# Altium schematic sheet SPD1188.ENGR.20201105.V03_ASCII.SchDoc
size A3; Revision: V03; SheetNumber: 1; SheetTotal: 1
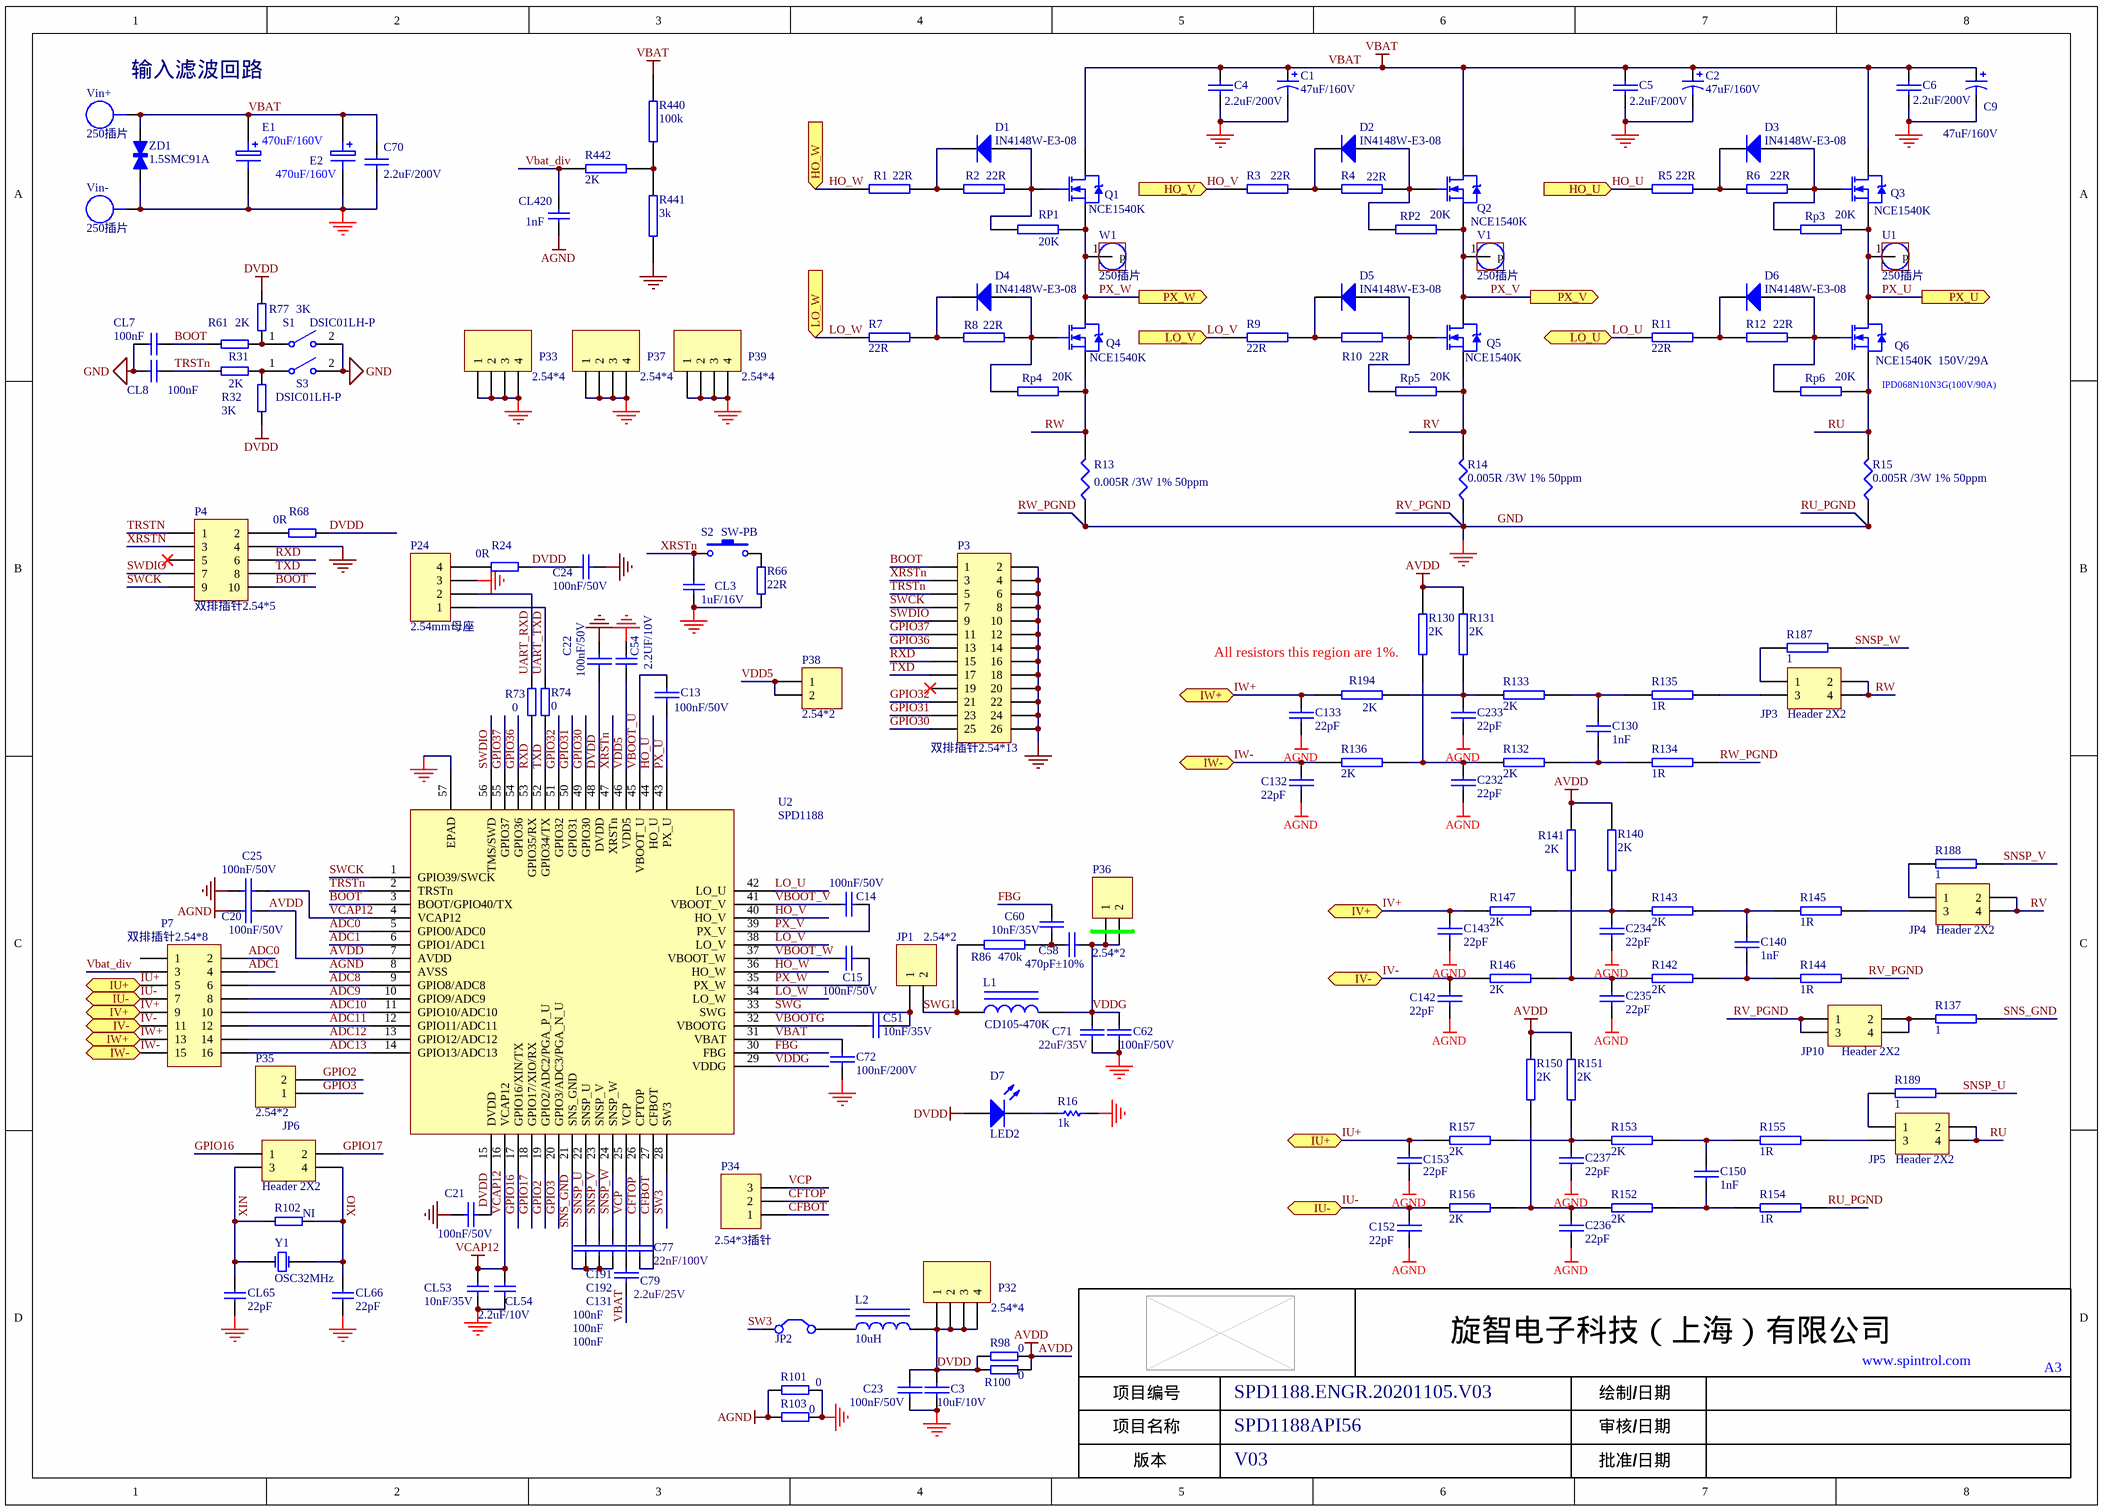
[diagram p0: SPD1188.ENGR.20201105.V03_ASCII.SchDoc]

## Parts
C1  47uF/160V  [RB5.0/10]
C2  47uF/160V  [RB5.0/10]
C3  10uF/10V  [0805]
C4  2.2uF/200V  [2220]
C5  2.2uF/200V  [2220]
C6  2.2uF/200V  [2220]
C9  47uF/160V  [RB5.0/10]
C13  100nF/50V  [0603]
C14  100nF/50V  [0603]
C15  100nF/50V  [0603]
C20  100nF/50V  [0603]
C21  100nF/50V  [0603]
C22  100nF/50V  [0603]
C23  100nF/50V  [0603]
C24  100nF/50V  [0603]
C25  100nF/50V  [0603]
C51  10nF/35V  [0603]
C54  2.2UF/10V  [0603]
C58  470pF±10%  [0603]
C60  10nF/35V  [0603]
C62  100nF/50V  [0603]
C70  2.2uF/200V  [2220]
C71  22uF/35V  [1206]
C72  100nF/200V  [1206]
C77  22nF/100V  [0805]
C79  2.2uF/25V  [0805]
C130  1nF  [0603]
C131  100nF  [0603]
C132  22pF  [0603]
C133  22pF  [0603]
C140  1nF  [0603]
C142  22pF  [0603]
C143  22pF  [0603]
C150  1nF  [0603]
C152  22pF  [0603]
C153  22pF  [0603]
C191  100nF  [0603]
C192  100nF  [0603]
C232  22pF  [0603]
C233  22pF  [0603]
C234  22pF  [0603]
C235  22pF  [0603]
C236  22pF  [0603]
C237  22pF  [0603]
CL3  1uF/16V  [0603]
CL7  100nF  [0603]
CL8  100nF  [0603]
CL53  10nF/35V  [0603]
CL54  2.2uF/10V  [0603]
CL65  CAP CER 20PF 10V  [0603]  (value not drawn)
CL66  CAP CER 20PF 10V  [0603]  (value not drawn)
CL420  1nF  [0603]
D1  IN4148W-E3-08  [LL-34]
D2  IN4148W-E3-08  [LL-34]
D3  IN4148W-E3-08  [LL-34]
D4  IN4148W-E3-08  [LL-34]
D5  IN4148W-E3-08  [LL-34]
D6  IN4148W-E3-08  [LL-34]
D7  LED2  [LED0805]
E1  470uF/160V  [470uF_100V]
E2  470uF/160V  [470uF_100V]
JP1  2.54*2  [CON2]
JP2  Jumper  [CON2]  (value not drawn)
JP3  Header 2X2  [HDR2X2]
JP4  Header 2X2  [HDR2X2]
JP5  Header 2X2  [HDR2X2]
JP6  Header 2X2  [HDR2X2]
JP10  Header 2X2  [HDR2X2]
L1  CD105-470K  [CD105]
L2  10uH  [CD105]
P3  双排插针2.54*13  [HDR2X13]
P4  双排插针2.54*5  [HDR2X5]
P7  双排插针2.54*8  [HDR2X8]
P24  2.54mm母座  [HDR1X4]
P32  2.54*4  [HDR1X4]
P33  2.54*4  [HDR1X4]
P34  2.54*3插针  [2.54*3]
P35  2.54*2  [CON2]
P36  2.54*2  [CON2]
P37  2.54*4  [HDR1X4]
P38  2.54*2  [CON2]
P39  2.54*4  [HDR1X4]
Q1  NCE1540K  [TO-252]
Q2  NCE1540K  [TO-252]
Q3  NCE1540K  [TO-252]
Q4  NCE1540K  [TO-252]
Q5  NCE1540K  [TO-252]
Q6  NCE1540K  150V/29A  [TO-252]
R1  22R  [0603]
R2  22R  [0603]
R3  22R  [0603]
R4  22R  [0603]
R5  22R  [0603]
R6  22R  [0603]
R7  22R  [0603]
R8  22R  [0603]
R9  22R  [0603]
R10  22R  [0603]
R11  22R  [0603]
R12  22R  [0603]
R13  0.005R /3W 1% 50ppm  [2512]
R14  0.005R /3W 1% 50ppm  [2512]
R15  0.005R /3W 1% 50ppm  [2512]
R16  1k  [0603]
R24  0R  [0603]
R31  2K  [0603]
R32  3K  [0603]
R61  2K  [0603]
R66  22R  [0603]
R68  0R  [0603]
R73  RES SMD 0.0OHM  [0603]  (value not drawn)
R74  RES SMD 0.0OHM  [0603]  (value not drawn)
R77  3K  [0603]
R86  470k  [0603]
R98  RES SMD 0.0OHM  [0603]  (value not drawn)
R100  RES SMD 0.0OHM  [0603]  (value not drawn)
R101  RES SMD 0.0OHM  [0603]  (value not drawn)
R102  NI  [0603]
R103  RES SMD 0.0OHM  [0603]  (value not drawn)
R130  2K  [0603]
R131  2K  [0603]
R132  2K  [0603]
R133  2K  [0603]
R134  1R  [0603]
R135  1R  [0603]
R136  2K  [0603]
R137  1  [0603]
R140  2K  [0603]
R141  2K  [0603]
R142  2K  [0603]
R143  2K  [0603]
R144  1R  [0603]
R145  1R  [0603]
R146  2K  [0603]
R147  2K  [0603]
R150  2K  [0603]
R151  2K  [0603]
R152  2K  [0603]
R153  2K  [0603]
R154  1R  [0603]
R155  1R  [0603]
R156  2K  [0603]
R157  2K  [0603]
R187  1  [0603]
R188  1  [0603]
R189  1  [0603]
R194  2K  [0603]
R440  100k  [0805]
R441  3k  [0603]
R442  2K  [0603]
RP1  20K  [0603]
RP2  20K  [0603]
Rp3  20K  [0603]
Rp4  20K  [0603]
Rp5  20K  [0603]
Rp6  20K  [0603]
S1  DSIC01LH-P  [S7.62*1]
S2  SW-PB  [SWITCH-4]
S3  DSIC01LH-P  [S7.62*1]
U1  250插片  [PIN_L]
U2  SPD1188  [QFN56L_20190222]
V1  250插片  [PIN_L]
Vin+  250插片  [PIN_L]
Vin-  250插片  [PIN_L]
W1  250插片  [PIN_L]
Y1  OSC32MHz  [OSC]
ZD1  1.5SMC91A  [SMCTVS]

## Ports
HO_U (in), HO_V (in), HO_W (in), IU+ (bidir), IU- (bidir), IV+ (bidir), IV- (bidir), IW+ (bidir), IW- (bidir), LO_U (bidir), LO_V (in), LO_W (in), PX_U (out), PX_V (out), PX_W (out)

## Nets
AGND: C20.1 C132.2 C133.2 C142.2 C143.2 C152.2 C153.2 C232.2 C233.1 C234.2 C235.1 C236.2 C237.1 CL420.1 R101.2 R103.2 U2.8(AVSS)
AVDD: C20.2 R98.1 R100.1 R130.2 R131.2 R140.1 R141.2 R150.2 R151.2 U2.7(AVDD)
DVDD: C3.2 C21.2 C22.2 C23.2 C24.2 D7.1(A) L2.2 P32.1 P32.2 P32.3 P32.4 R24.2 R32.1 R68.2 R77.1 R98.2 R100.2 U2.15(DVDD) U2.48(DVDD)
GND: C1.2 C2.2 C3.1 C4.2 C5.2 C6.2 C9.2 C21.1 C22.1 C23.1 C24.1 C25.1 C54.1 C62.1 C70.2 C71.2 C72.2 CL3.1 CL7.2 CL8.2 CL53.1 CL54.1 CL65.1 CL66.1 E1.2 E2.2 JP10.1 JP10.3 P3.2 P3.4 P3.6 P3.8 P3.10 P3.12 P3.14 P3.16 P3.18 P3.20 P3.22 P3.24 P3.26 P4.4 P24.3 P33.1 P33.2 P33.3 P33.4 P37.1 P37.2 P37.3 P37.4 P39.1 P39.2 P39.3 P39.4 R13.1 R14.1 R15.1 R16.1 R66.2 R101.1 R103.1 R134.1 R144.1 R154.1 R441.1 S1.2 S3.2 U2.57(EPAD) Vin-.1 ZD1.2  [also labelled RU_PGND, RV_PGND, RW_PGND]
VBAT: C1.1 C2.1 C4.1 C5.1 C6.1 C9.1 C70.1 C72.1 C79.2 E1.1 E2.1 Q1.2(D) Q2.2(D) Q3.2(D) R440.2 U2.31(VBAT) Vin+.1 ZD1.1
VCAP12: C25.2 CL53.2 CL54.2 U2.4(VCAP12) U2.16(VCAP12)
ADC0: P7.2 U2.5(GPIO0/ADC0)
ADC1: P7.4 U2.6(GPIO1/ADC1)
ADC8: P7.6 U2.9(GPIO8/ADC8)
ADC9: P7.8 U2.10(GPIO9/ADC9)
ADC10: P7.10 U2.11(GPIO10/ADC10)
ADC11: P7.12 U2.12(GPIO11/ADC11)
ADC12: P7.14 U2.13(GPIO12/ADC12)
ADC13: P7.16 U2.14(GPIO13/ADC13)
BOOT: CL7.1 P3.1 P4.10 R61.1 U2.3(BOOT/GPIO40/TX)
CFBOT: C77.2 P34.1 U2.27(CFBOT)
CFTOP: C77.1 P34.2 U2.26(CPTOP)
FBG: C60.2 U2.30(FBG)
GPIO2: P35.2 U2.19(GPIO2/ADC2/PGA_P_U)
GPIO3: P35.1 U2.20(GPIO3/ADC3/PGA_N_U)
GPIO16: JP6.1 U2.17(GPIO16/XIN/TX)
GPIO17: JP6.2 U2.18(GPIO17/XIO/RX)
GPIO30: P3.25 U2.49(GPIO30)
GPIO31: P3.23 U2.50(GPIO31)
GPIO32: P3.21 U2.51(GPIO32)
GPIO36: P3.13 U2.54(GPIO36)
GPIO37: P3.11 U2.55(GPIO37)
HO_U: R5.1 U2.44(HO_U) ; port HO_U
HO_V: R3.1 U2.40(HO_V) ; port HO_V
HO_W: R1.1 U2.36(HO_W) ; port HO_W
IU+: C153.1 P7.5 R157.2 ; port IU+
IU-: C152.1 P7.7 R156.2 ; port IU-
IV+: C143.1 P7.9 R147.2 ; port IV+
IV-: C142.1 P7.11 R146.2 ; port IV-
IW+: C133.1 P7.13 R194.2 ; port IW+
IW-: C132.1 P7.15 R136.2 ; port IW-
LO_U: R11.1 U2.42(LO_U) ; port LO_U
LO_V: R9.1 U2.38(LO_V) ; port LO_V
LO_W: R7.1 U2.34(LO_W) ; port LO_W
PX_U: C13.2 Q3.3(S) Q6.2(D) Rp3.2 U1.1(p) U2.43(PX_U) ; port PX_U
PX_V: C14.2 Q2.3(S) Q5.2(D) RP2.2 U2.39(PX_V) V1.1(p) ; port PX_V
PX_W: C15.2 Q1.3(S) Q4.2(D) RP1.2 U2.35(PX_W) W1.1(p) ; port PX_W
RU: JP5.2 JP5.4 Q6.3(S) R15.2 Rp6.2
RV: JP4.2 JP4.4 Q5.3(S) R14.2 Rp5.2
RW: JP3.2 JP3.4 Q4.3(S) R13.2 Rp4.2
RXD: P3.15 P4.6 R73.2 U2.53(GPIO35/RX)
SNS_GND: C131.2 C191.2 C192.2 R137.2 U2.21(SNS_GND)
SNSP_U: C131.1 R189.2 U2.22(SNSP_U)
SNSP_V: C192.1 R188.2 U2.23(SNSP_V)
SNSP_W: C191.1 R187.2 U2.24(SNSP_W)
SW3: JP2.2(C2) U2.28(SW3)
SWCK: P3.7 P4.9 U2.1(GPIO39/SWCK)
SWDIO: P3.9 P4.7 U2.56(TMS/SWD)
SWG: C51.1 JP1.1 U2.33(SWG)
SWG1: JP1.2 L1.1 R86.2
TRSTn: CL8.1 P3.5 P4.1 R31.1 U2.2(TRSTn)
TXD: P3.17 P4.8 R74.2 U2.52(GPIO34/TX)
UART_RXD: P24.2 R73.1
UART_TXD: P24.1 R74.1
Vbat_div: CL420.2 P7.3 R442.1
VBOOT_U: C13.1 U2.45(VBOOT_U)
VBOOT_V: C14.1 U2.41(VBOOT_V)
VBOOT_W: C15.1 U2.37(VBOOT_W)
VBOOTG: C51.2 U2.32(VBOOTG)
VCP: C79.1 P34.3 U2.25(VCP)
VDD5: C54.2 P38.1 P38.2 U2.46(VDD5)
VDDG: C58.2 C62.2 C71.1 L1.2 P36.1 P36.2 U2.29(VDDG)
XIN: CL65.2 JP6.3 R102.1 Y1.1(OSC1)
XIO: CL66.2 JP6.4 R102.2 Y1.2(OSC2)
XRSTn: CL3.2 P3.3 P4.3 S2.1 U2.47(XRSTn)
NetC58_1: C58.1 C60.1 R86.1
NetC130_1: C130.1 R133.1 R135.2
NetC130_2: C130.2 R132.1 R134.2
NetC140_1: C140.1 R143.1 R145.2
NetC140_2: C140.2 R142.1 R144.2
NetC150_1: C150.1 R153.1 R155.2
NetC150_2: C150.2 R152.1 R154.2
NetC232_1: C232.1 R130.1 R132.2 R136.1
NetC233_2: C233.2 R131.1 R133.2 R194.1
NetC234_1: C234.1 R140.2 R143.2 R147.1
NetC235_2: C235.2 R141.1 R142.2 R146.1
NetC236_1: C236.1 R150.1 R152.2 R156.1
NetC237_2: C237.2 R151.1 R153.2 R157.1
NetD1_1: D1.1(A) Q1.1(G) R2.2 RP1.1
NetD1_2: D1.2(K) R1.2 R2.1
NetD2_1: D2.1(A) Q2.1(G) R4.2 RP2.1
NetD2_2: D2.2(K) R3.2 R4.1
NetD3_1: D3.1(A) Q3.1(G) R6.2 Rp3.1
NetD3_2: D3.2(K) R5.2 R6.1
NetD4_1: D4.1(A) Q4.1(G) R8.2 Rp4.1
NetD4_2: D4.2(K) R7.2 R8.1
NetD5_1: D5.1(A) Q5.1(G) R10.2 Rp5.1
NetD5_2: D5.2(K) R9.2 R10.1
NetD6_1: D6.1(A) Q6.1(G) R12.2 Rp6.1
NetD6_2: D6.2(K) R11.2 R12.1
NetD7_2: D7.2(K) R16.2
NetJP2_1: JP2.1(C1) L2.1
NetJP3_1: JP3.1 R187.1
NetJP3_3: JP3.3 R135.1
NetJP4_1: JP4.1 R188.1
NetJP4_3: JP4.3 R145.1
NetJP5_1: JP5.1 R189.1
NetJP5_3: JP5.3 R155.1
NetJP10_2: JP10.2 JP10.4 R137.1
NetP4_2: P4.2 R68.1
NetP24_4: P24.4 R24.1
NetR31_2: R31.2 R32.2 S3.1
NetR61_2: R61.2 R77.2 S1.1
NetR66_1: R66.1 S2.2
NetR440_1: R440.1 R441.2 R442.2

Not connected (* = marked no-connect by the designer): P3 19*; P4 5*; P7 1

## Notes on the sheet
- (near Vin+) 输入滤波回路
- IPD068N10N3G(100V/90A)
- (near R130) All resistors this region are 1%.
- SPD1188.ENGR.20201105.V03
- SPD1188API56
- V03

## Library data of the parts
C1 C2 C9 = Cap Pol1: Polarized Capacitor (Radial); Value: 47uF
C3-C6 C13-C15 C20-C25 C51 C58 C60 C70-C72 C77 C79 C130-C133 C140 C142 C143 C150 C152 C153 C191 C192 C232-C237 = CAP: Capacitor
C54 CL54 CL420 = Capacitor Unpolarized: CAP CER 2.2UF 10V X7R 0603
C62 = CAP: AR02010135A0
CL3 = Capacitor Unpolarized: CAP CER 1UF 16V X7R 0603
CL7 CL8 = Capacitor Unpolarized: Unpolarized Capacitor
CL53 = Capacitor Unpolarized: CAP CER 10000PF 10V X7R 0603
CL65 CL66 = Capacitor Unpolarized: CAP CER 20PF 10V X7R 0603
D1-D6 = Diode: Default Diode
D7 = LED2: Typical RED, GREEN, YELLOW, AMBER GaAs LED
E1 E2 = CAP-EC: 100PX471MEFC16*25  rubycon
JP1 P35 P36 P38 = Header 2: Header, 2-Pin
JP2 = Jumper: Jumper Wire
JP3-JP6 JP10 = Header 2X2: Header, 2-Pin, Dual row
L1 = Inductor Iron: Magnetic-Core Inductor; Value: 47uH
L2 = Inductor Iron: Magnetic-Core Inductor
P3 = Header 13X2: Header, 13-Pin, Dual row
P4 = Header 5X2: Header, 5-Pin, Dual row
P7 = Header 8X2: Header, 8-Pin, Dual row
P24 P32 P33 P37 P39 = Header 4: Header, 4-Pin
P34 = Header 3: A9TS21-0011
Q1-Q6 = IRF1010E: HEXFET Power MOSFET; Note: Pin 2 is electrically connected to pin 4.; Sim Note: Thermal Model provided is not called on from main Subckt.
R1-R12 R86 R130-R137 R140-R147 R150-R157 R187-R189 R194 R440-R442 RP1 RP2 Rp3-Rp6 = RES2
R13-R15 = RES1
R16 = Res1: Resistor
R24 R31 R32 R61 R68 R77 R102 = Resistor
R66 = Resistor: RES SMD 100 OHM 1% 1/10W
R73 R74 R98 R100 R101 R103 = Resistor: RES SMD 0.0OHM JUMPER 1/10W
S1 S3 = SW-2
S2 = SW-PB: Switch Key
U1 V1 W1 = TP
U2 = SPD1188: 32-bit MCU with  Motor Pre-driver and power
Vin+ Vin- = PAD: TE
Y1 = OSC32MHz: CRYSTAL 32.0000MHZ 20PF T/H
ZD1 = TVS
